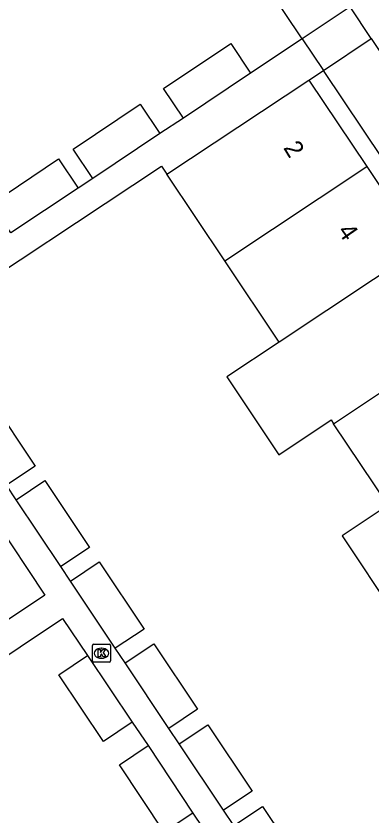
# Model space of a CAD drawing. Extents: x 158352 to 159489, y 383828 to 384597.
# Drawn here: x 158865.77 to 158885.39, y 384412.12 to 384456.23 of the extents above; entities that cross this region are included whole.
import ezdxf

# ---------------------------------------------------------------- set-up
doc = ezdxf.new("R2010")
doc.units = 0
for name, color, linetype in [('IMGEO_Erf', 7, 'Continuous'), ('IMGEO_Kolk', 7, 'Continuous'), ('IMGEO_Pand', 7, 'Continuous'), ('IMGEO_Pand_nummerreeks', 7, 'Continuous'), ('IMGEO_Voetpad_open', 7, 'Continuous')]:
    doc.layers.add(name, color=color, linetype=linetype)

msp = doc.modelspace()

# ---------------------------------------------------------------- linework, layer by layer
at = {"layer": 'IMGEO_Erf'}
for points in [[(158881.542, 384454.976), (158866.797, 384476.999)], [(158958.047, 384340.708), (158896.943, 384431.973), (158882.708, 384453.235)]]:
    msp.add_lwpolyline(points, dxfattribs=at)
at = {"layer": 'IMGEO_Kolk'}
for p, q in [((158869.981, 384420.671), (158869.981, 384421.523)), ((158870.056, 384421.597), (158870.908, 384421.597)), ((158870.982, 384421.523), (158870.982, 384420.671)), ((158870.469, 384421.377), (158870.494, 384421.377)), ((158870.492, 384420.817), (158870.467, 384420.817)), ((158870.908, 384420.597), (158870.056, 384420.597))]:
    msp.add_line(p, q, dxfattribs=at)
for points in [[(158869.981, 384420.671), (158869.981, 384421.523)], [(158870.056, 384421.597), (158870.908, 384421.597)], [(158870.982, 384421.523), (158870.982, 384420.671)], [(158870.302, 384421.297), (158870.425, 384421.297), (158870.425, 384421.146), (158870.555, 384421.297), (158870.719, 384421.297), (158870.573, 384421.146), (158870.726, 384420.897), (158870.574, 384420.897), (158870.489, 384421.061), (158870.425, 384420.994), (158870.425, 384420.897), (158870.302, 384420.897), (158870.302, 384421.297)], [(158870.908, 384420.597), (158870.056, 384420.597)]]:
    msp.add_lwpolyline(points, dxfattribs=at)
for centre, start, end in [((158870.058, 384421.521), 91.552, 178.448), ((158870.058, 384421.521), 91.552, 178.448), ((158870.906, 384421.521), 1.552, 88.448), ((158870.906, 384421.521), 1.552, 88.448), ((158870.058, 384420.673), 181.552, 268.448), ((158870.058, 384420.673), 181.552, 268.448), ((158870.906, 384420.673), 271.552, 358.448), ((158870.906, 384420.673), 271.552, 358.448)]:
    msp.add_arc(centre, 0.0765, start, end, dxfattribs=at)
for centre, major_axis, ratio, start_param, end_param in [((158870.468, 384421.097), (-0.387, 0.002), 0.722429, 4.712389, 7.853982), ((158870.493, 384421.097), (-0.39, 0.002), 0.717154, 1.570796, 4.712389)]:
    msp.add_ellipse(centre, major_axis=major_axis, ratio=ratio, start_param=start_param, end_param=end_param, dxfattribs=at)
at = {"layer": 'IMGEO_Pand'}
for points in [[(158874.996, 384450.606), (158873.906, 384452.231), (158877.603, 384454.709), (158878.7, 384453.073)], [(158878.7, 384453.073), (158874.996, 384450.606)], [(158874.09, 384447.51), (158881.915, 384452.704)], [(158881.915, 384452.704), (158885.098, 384447.937)], [(158870.003, 384447.28), (158868.923, 384448.89), (158872.619, 384451.368), (158873.706, 384449.747)], [(158873.706, 384449.747), (158870.003, 384447.28)], [(158865.492, 384444.275), (158864.421, 384445.872), (158868.117, 384448.35), (158869.195, 384446.742)], [(158877.282, 384442.729), (158885.098, 384447.937)], [(158885.098, 384447.937), (158888.089, 384443.457)], [(158877.282, 384442.729), (158874.09, 384447.51)], [(158869.195, 384446.742), (158865.492, 384444.275)], [(158888.089, 384443.457), (158880.272, 384438.249)], [(158880.272, 384438.249), (158877.282, 384442.729)], [(158883.272, 384433.755), (158891.089, 384438.962)], [(158880.272, 384438.249), (158877.396, 384436.329), (158880.26, 384432.037), (158883.137, 384433.958), (158883.272, 384433.755)], [(158862.793, 384434.029), (158864.373, 384435.085), (158866.83, 384431.412), (158865.251, 384430.356)], [(158886.273, 384429.26), (158883.272, 384433.755)], [(158865.783, 384429.557), (158867.363, 384430.613), (158869.819, 384426.934), (158868.239, 384425.879)], [(158868.239, 384425.879), (158865.783, 384429.557)], [(158886.273, 384429.26), (158883.741, 384427.573), (158886.635, 384423.238), (158889.165, 384424.926), (158889.263, 384424.78)], [(158868.777, 384425.077), (158870.356, 384426.129), (158872.827, 384422.43), (158871.247, 384421.375)], [(158871.247, 384421.375), (158868.777, 384425.077)], [(158871.788, 384420.567), (158873.366, 384421.619), (158875.777, 384418.007), (158874.196, 384416.953)], [(158872.17, 384417.289), (158870.591, 384416.233), (158868.129, 384419.915), (158869.709, 384420.971)], [(158869.709, 384420.971), (158872.17, 384417.289)], [(158874.196, 384416.953), (158871.788, 384420.567)], [(158874.77, 384416.094), (158876.351, 384417.147), (158878.786, 384413.498), (158877.203, 384412.443)], [(158875.511, 384412.288), (158873.932, 384411.231), (158871.473, 384414.946), (158873.052, 384416.003)], [(158873.052, 384416.003), (158875.511, 384412.288)], [(158877.203, 384412.443), (158874.77, 384416.094)], [(158877.767, 384411.592), (158879.351, 384412.652), (158881.773, 384409.023), (158880.196, 384407.966)]]:
    msp.add_lwpolyline(points, dxfattribs=at)
at = {"layer": 'IMGEO_Voetpad_open'}
for points in [[(158884.184, 384456.734), (158881.542, 384454.976)], [(158885.345, 384454.99), (158884.184, 384456.734)], [(158881.542, 384454.976), (158878.7, 384453.073)], [(158881.542, 384454.976), (158882.708, 384453.235)], [(158882.708, 384453.235), (158885.345, 384454.99)], [(158885.345, 384454.99), (158899.598, 384433.573), (158960.345, 384342.297)], [(158881.915, 384452.704), (158882.708, 384453.235)], [(158874.996, 384450.606), (158873.706, 384449.747)], [(158861.31, 384439.679), (158873.799, 384447.946), (158874.09, 384447.51)], [(158870.003, 384447.28), (158869.195, 384446.742)], [(158865.783, 384429.557), (158865.251, 384430.356)], [(158864.569, 384428.486), (158867.368, 384424.298), (158850.486, 384413.028), (158847.695, 384417.215)], [(158868.777, 384425.077), (158868.239, 384425.879)], [(158854.372, 384413.675), (158868.332, 384423.007), (158869.709, 384420.971)], [(158871.788, 384420.567), (158871.247, 384421.375)], [(158872.17, 384417.289), (158873.052, 384416.003)], [(158874.77, 384416.094), (158874.196, 384416.953)], [(158875.511, 384412.288), (158876.048, 384411.482)], [(158877.767, 384411.592), (158877.203, 384412.443)]]:
    msp.add_lwpolyline(points, dxfattribs=at)

# ---------------------------------------------------------------- texts
at = {"layer": 'IMGEO_Pand_nummerreeks'}
for s, rotation, p in [('2', 301.3821, (158880.478, 384448.969)), ('4', 304.7805, (158883.456, 384444.367))]:
    msp.add_text(s, height=1, rotation=rotation, dxfattribs=at).set_placement(p)

doc.saveas('drawing.dxf')
